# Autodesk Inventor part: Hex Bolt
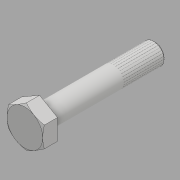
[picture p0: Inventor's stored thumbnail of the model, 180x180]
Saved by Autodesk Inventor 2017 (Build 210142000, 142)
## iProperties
Created: 2016-05
Part Number: Hex Bolt
Material: Generic
Document SubType Name: Modeling
Designer: CADCIM
Density: 1 g/cm^3
Appearance: Default
Author: CADCIM
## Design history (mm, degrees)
sketch "Sketch1"
  geometry: L1 (0, -19.63)-(-17, -9.815); L2 (-17, -9.815)-(-17, 9.815); L3 (-17, 9.815)-(0, 19.63); L4 (0, 19.63)-(17, 9.815); L5 (17, 9.815)-(17, -9.815); L6 (17, -9.815)-(0, -19.63); 2 further points
  constraints: 12 end point, 1 coincident, 13 other
  dimensions: "d0" = 34 distance between parallel lines of L2 L5
extrude "Extrusion1" new body sketch "Sketch1" distance "d1" = 14; taper "d2" = 0 deg
sketch "Sketch2"
  geometry: 1 further point
sketch "Sketch3"
  geometry: C1 r 10 at (0, 0); 1 further point
  constraints: 1 centre point, 1 coincident
  dimensions: "d3" = 20 diameter of C1
extrude "Extrusion2" join sketch "Sketch3" distance "d4" = 110; taper "d5" = 0 deg
thread "Thread1" dims "d6" = 40, "d7" = 0
sketch "Sketch4"
  geometry: L1 (0, -19.63)-(17, -9.815) reference; C1 r 17 at (0, 0); 1 further point
  constraints: 1 centre point, 1 coincident, 1 tangent
extrude "Extrusion3" sketch "Sketch4" distance "d8" = 200; taper "d9" = 60 deg
chamfer "Chamfer1" distance "d10" = 1.5; stored, may be unused: second distance "d11" = 2, angle "d12" = 45 deg
body "Solid1"
